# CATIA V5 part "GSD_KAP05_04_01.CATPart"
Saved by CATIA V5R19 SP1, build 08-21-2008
Part number: GSD_KAP05_04_01
Definition: Beispielmodell: Linien erzeugen
Description: CATIA V5 Flächenmodellierung  Copyright (c) 2009 Maik Hertha IT Consultants
Bounding box of the stored display mesh (mm): x 0 to 50, y 0 to 50, z 0 to 0
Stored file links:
  \GSD_BUCH_UEBUNG\GSD_KAP05_04_01.CATPart
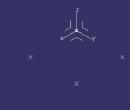
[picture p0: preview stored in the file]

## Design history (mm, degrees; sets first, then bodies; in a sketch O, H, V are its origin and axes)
AxisSystem1: origin (0, 0, 0), X (1, 0, 0), Y (0, 1, 0), Z (0, 0, 1)
Set1
  Point1: (0, 0, 0), in AxisSystem1
  Point2: (50, 0, 0), relative to Point1, in AxisSystem1
  Point3: (0, 50, 0), relative to Point2, in AxisSystem1
  Point4: (-50, 0, 0), relative to Point3, in AxisSystem1
Body1 (main body)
